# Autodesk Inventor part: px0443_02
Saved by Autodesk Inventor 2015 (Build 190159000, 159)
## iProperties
Created: 2019-05
Part Number: px0443_02
Checked By: TraceParts S.A.
Material: Generic
Catalog Web Link: www.traceparts.com
Document SubType Name: Modeling
Designer: TraceParts
Density: 1 g/cm^3
Appearance: Default
Company: TraceParts S.A.
Author: TraceParts
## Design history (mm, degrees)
feature "px0443_02.ipt"
body "Solid1"
